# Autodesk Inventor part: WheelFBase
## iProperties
Created: 2010-08
Part Number: WheelFBase
Document SubType Name: Modeling
Designer: nguyenducthang
Density: 1 g/cm^3
Mass: 111.723 g
Surface Area: 390.736 cm^2
Volume: 111.723 cm^3
Author: nguyenducthang
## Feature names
1. Revolution7
2. Coil9
3. Extrusion65
